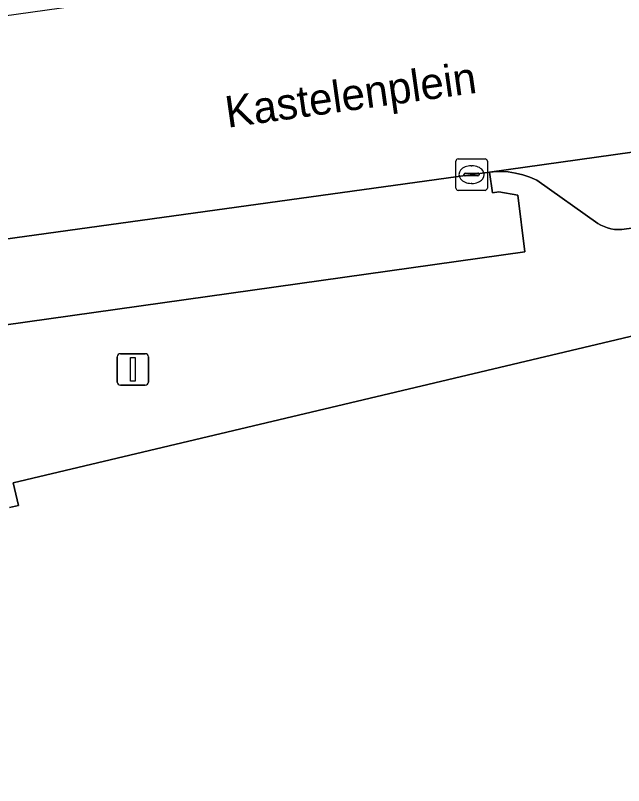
# Model space of a CAD drawing. Extents: x 158031 to 159244, y 380104 to 381214.
# Drawn here: x 158709.76 to 158729.06, y 381134.96 to 381159.42 of the extents above; entities that cross this region are included whole.
import ezdxf

# ---------------------------------------------------------------- set-up
doc = ezdxf.new("R2010")
doc.units = 0
for name, color, linetype in [('IMGEO_Kolk', 7, 'Continuous'), ('IMGEO_Openbare_ruimte_label', 7, 'Continuous'), ('IMGEO_Pand', 7, 'Continuous'), ('IMGEO_Parkeervlak_gesloten', 7, 'Continuous'), ('IMGEO_Parkeervlak_open', 7, 'Continuous'), ('IMGEO_Rijbaan_lokaal_open', 7, 'Continuous'), ('IMGEO_Verkeersbordpaal', 7, 'Continuous'), ('IMGEO_Voetpad_open', 7, 'Continuous')]:
    doc.layers.add(name, color=color, linetype=linetype)

msp = doc.modelspace()

# ---------------------------------------------------------------- linework, layer by layer
at = {"layer": 'IMGEO_Kolk'}
for p, q in [((158723.738, 381153.937), (158723.738, 381154.789)), ((158723.813, 381154.863), (158724.665, 381154.863)), ((158724.739, 381154.789), (158724.739, 381153.937)), ((158724.04, 381154.406), (158724.438, 381154.406)), ((158724.226, 381154.643), (158724.251, 381154.643)), ((158723.997, 381154.357), (158723.997, 381154.369)), ((158724.435, 381154.32), (158724.037, 381154.32)), ((158724.481, 381154.369), (158724.481, 381154.357)), ((158724.249, 381154.083), (158724.224, 381154.083)), ((158724.665, 381153.863), (158723.813, 381153.863))]:
    msp.add_line(p, q, dxfattribs=at)
for points in [[(158723.738, 381153.937), (158723.738, 381154.789)], [(158723.813, 381154.863), (158724.665, 381154.863)], [(158724.739, 381154.789), (158724.739, 381153.937)], [(158724.665, 381153.863), (158723.813, 381153.863)]]:
    msp.add_lwpolyline(points, dxfattribs=at)
for centre, radius, start, end in [((158723.815, 381154.787), 0.0765, 91.552, 178.448), ((158723.815, 381154.787), 0.0765, 91.552, 178.448), ((158724.663, 381154.787), 0.0765, 1.552, 88.448), ((158724.663, 381154.787), 0.0765, 1.552, 88.448), ((158724.037, 381154.366), 0.0403, 85.8775, 175.7526), ((158724.442, 381154.368), 0.0386, 1.7309, 96.639), ((158724.034, 381154.356), 0.0366, 178.938, 274.7102), ((158724.438, 381154.363), 0.043, 264.8664, 352.4533), ((158723.815, 381153.939), 0.0765, 181.552, 268.448), ((158723.815, 381153.939), 0.0765, 181.552, 268.448), ((158724.663, 381153.939), 0.0765, 271.552, 358.448), ((158724.663, 381153.939), 0.0765, 271.552, 358.448)]:
    msp.add_arc(centre, radius, start, end, dxfattribs=at)
for centre, major_axis, ratio, start_param, end_param in [((158724.225, 381154.363), (-0.387, 0.002), 0.722429, 4.712389, 7.853982), ((158724.25, 381154.363), (-0.39, 0.002), 0.717154, 1.570796, 4.712389)]:
    msp.add_ellipse(centre, major_axis=major_axis, ratio=ratio, start_param=start_param, end_param=end_param, dxfattribs=at)
at = {"layer": 'IMGEO_Pand'}
msp.add_lwpolyline([(158749.63, 381092.137), (158747.942, 381099.262), (158750.828, 381103.72), (158743.55, 381134.428), (158743.202, 381135.921), (158739.534, 381151.662), (158709.69, 381144.574), (158709.861, 381143.861), (158709.57, 381143.791)], dxfattribs=at)
at = {"layer": 'IMGEO_Parkeervlak_gesloten'}
for points in [[(158725.932, 381151.909), (158725.707, 381153.706), (158725.106, 381153.815), (158724.899, 381153.787), (158724.803, 381154.439), (158704.376, 381151.612), (158699.52, 381150.945)], [(158698.165, 381150.124), (158698.105, 381150.029), (158697.107, 381148.462), (158697.068, 381148.41), (158697.04, 381148.378), (158697.131, 381147.854), (158725.932, 381151.909)]]:
    msp.add_lwpolyline(points, dxfattribs=at)
at = {"layer": 'IMGEO_Parkeervlak_open'}
msp.add_lwpolyline([(158746.075, 381157.143), (158746.032, 381157.46), (158738.547, 381156.368), (158738.395, 381156.347), (158724.803, 381154.439), (158724.92, 381154.451), (158725.159, 381154.459), (158725.398, 381154.446), (158725.634, 381154.412), (158725.866, 381154.357), (158726.093, 381154.281), (158726.312, 381154.185), (158728.248, 381152.813), (158728.345, 381152.757), (158728.447, 381152.71), (158728.552, 381152.671), (158728.661, 381152.643), (158728.771, 381152.624), (158728.883, 381152.616), (158728.995, 381152.617), (158729.011, 381152.618), (158738.965, 381154.007), (158739.044, 381154.018), (158742.969, 381154.564)], dxfattribs=at)
at = {"layer": 'IMGEO_Rijbaan_lokaal_open'}
msp.add_lwpolyline([(158804.618, 381172.689), (158736.723, 381163.215), (158660.9, 381152.634), (158662.421, 381145.756), (158665.961, 381146.244), (158672.278, 381147.123), (158682.088, 381148.565), (158684.275, 381148.833), (158686.652, 381149.132), (158699.52, 381150.945), (158704.376, 381151.612), (158724.803, 381154.439), (158738.395, 381156.347), (158738.547, 381156.368), (158746.032, 381157.46), (158751.662, 381158.225)], dxfattribs=at)
at = {"layer": 'IMGEO_Verkeersbordpaal'}
for p, q in [((158712.991, 381147.777), (158712.991, 381148.577)), ((158712.991, 381148.577), (158712.991, 381147.777)), ((158713.091, 381148.677), (158713.881, 381148.677)), ((158713.881, 381148.677), (158713.091, 381148.677)), ((158713.981, 381148.577), (158713.981, 381147.777)), ((158713.981, 381147.777), (158713.981, 381148.577)), ((158713.881, 381147.677), (158713.091, 381147.677)), ((158713.091, 381147.677), (158713.881, 381147.677))]:
    msp.add_line(p, q, dxfattribs=at)
msp.add_lwpolyline([(158713.411, 381148.552), (158713.561, 381148.552), (158713.561, 381147.802), (158713.411, 381147.802), (158713.411, 381148.552)], dxfattribs=at)
for centre, start, end in [((158713.091, 381148.577), 90, 180), ((158713.091, 381148.577), 90, 180), ((158713.881, 381148.577), 0, 90), ((158713.881, 381148.577), 360, 90), ((158713.091, 381147.777), 180, 270), ((158713.091, 381147.777), 180, 270), ((158713.881, 381147.777), 270, 0), ((158713.881, 381147.777), 270, 0)]:
    msp.add_arc(centre, 0.1, start, end, dxfattribs=at)
at = {"layer": 'IMGEO_Voetpad_open'}
for points in [[(158738.965, 381154.007), (158729.011, 381152.618), (158728.995, 381152.617), (158728.883, 381152.616), (158728.771, 381152.624), (158728.661, 381152.643), (158728.552, 381152.671), (158728.447, 381152.71), (158728.345, 381152.757), (158728.248, 381152.813), (158726.312, 381154.185), (158726.093, 381154.281), (158725.866, 381154.357), (158725.634, 381154.412), (158725.398, 381154.446), (158725.159, 381154.459), (158724.92, 381154.451), (158724.803, 381154.439), (158724.899, 381153.787), (158725.106, 381153.815), (158725.707, 381153.706), (158725.932, 381151.909), (158697.131, 381147.854)], [(158709.57, 381143.791), (158709.861, 381143.861), (158709.69, 381144.574), (158739.534, 381151.662), (158743.202, 381135.921), (158743.55, 381134.428), (158744.82, 381133.731), (158751.389, 381106.745)]]:
    msp.add_lwpolyline(points, dxfattribs=at)

# ---------------------------------------------------------------- texts
at = {"layer": 'IMGEO_Openbare_ruimte_label'}
msp.add_text('Kastelenplein', height=1, rotation=7.9923, dxfattribs=at).set_placement((158716.492, 381155.847))

doc.saveas('drawing.dxf')
